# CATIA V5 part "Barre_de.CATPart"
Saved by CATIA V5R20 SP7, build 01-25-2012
Part number: Barre_de
Bounding box of the stored display mesh (mm): x 0 to 15, y -28.028 to 29, z 39.309 to 57.103
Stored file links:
  G:\bon\Nouveau dossier\Barre_de.CATPart
  G:\bon\Nouveau dossier\cgirerd.CATProduct
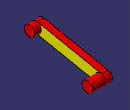
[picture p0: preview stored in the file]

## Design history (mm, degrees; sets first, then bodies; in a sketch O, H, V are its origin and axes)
Set1
  Point1 "D": linked copy from another document
  Point2 "E": linked copy from another document
Body1 (main body)
  Sketch1 on yz-plane, origin (0, 0, 0), H (0, 1, 0), V (0, 0, 1)
    arc A1 centre (-24.0283, 53.1108) radius 4 from (-23.2435, 57.033) to (-24.8131, 49.1885) ccw
    point P1 (-24.0283, 53.1108)
    reference projected point E1 (-24.0283, 53.1108) from Point1
    arc A2 centre (25, 43.3013) radius 4 from (24.2152, 39.379) to (25.7848, 47.2235) ccw
    point P2 (25, 43.3013)
    reference projected point E2 (25, 43.3013) from Point2
    line L1 (-23.2435, 57.033) -> (25.7848, 47.2235)
    line L2 (24.2152, 39.379) -> (-24.8131, 49.1885)
    radius A1 = 4
    radius A2 = 4
    coincidence: P1 E1, E2 P2
    tangency: L1 A1, A2 L1, A2 L2, L2 A1
  Pad1: profile Sketch1, direction (1, 0, 0), length 5
  Sketch2 on end face of Pad1, origin (5, 0, 0), H (0, 1, 0), V (0, 0, 1)
    circle A1 centre (-24.0283, 53.1108) radius 4
    point P1 (-24.0283, 53.1108)
    reference projected point E1 (-24.0283, 53.1108) from Point1
    radius A1 = 4
    coincidence: P1 E1
  Pad2: profile Sketch2, direction (1, 0, 0), length 5
  Sketch3 on end face of Pad1, origin (5, 0, 0), H (0, 1, 0), V (0, 0, 1)
    circle A1 centre (25, 43.3013) radius 4
    point P1 (25, 43.3013)
    reference projected point E1 (25, 43.3013) from Point2
    radius A1 = 4
    coincidence: P1 E1
  Pad3: profile Sketch3, direction (1, 0, 0), length 10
